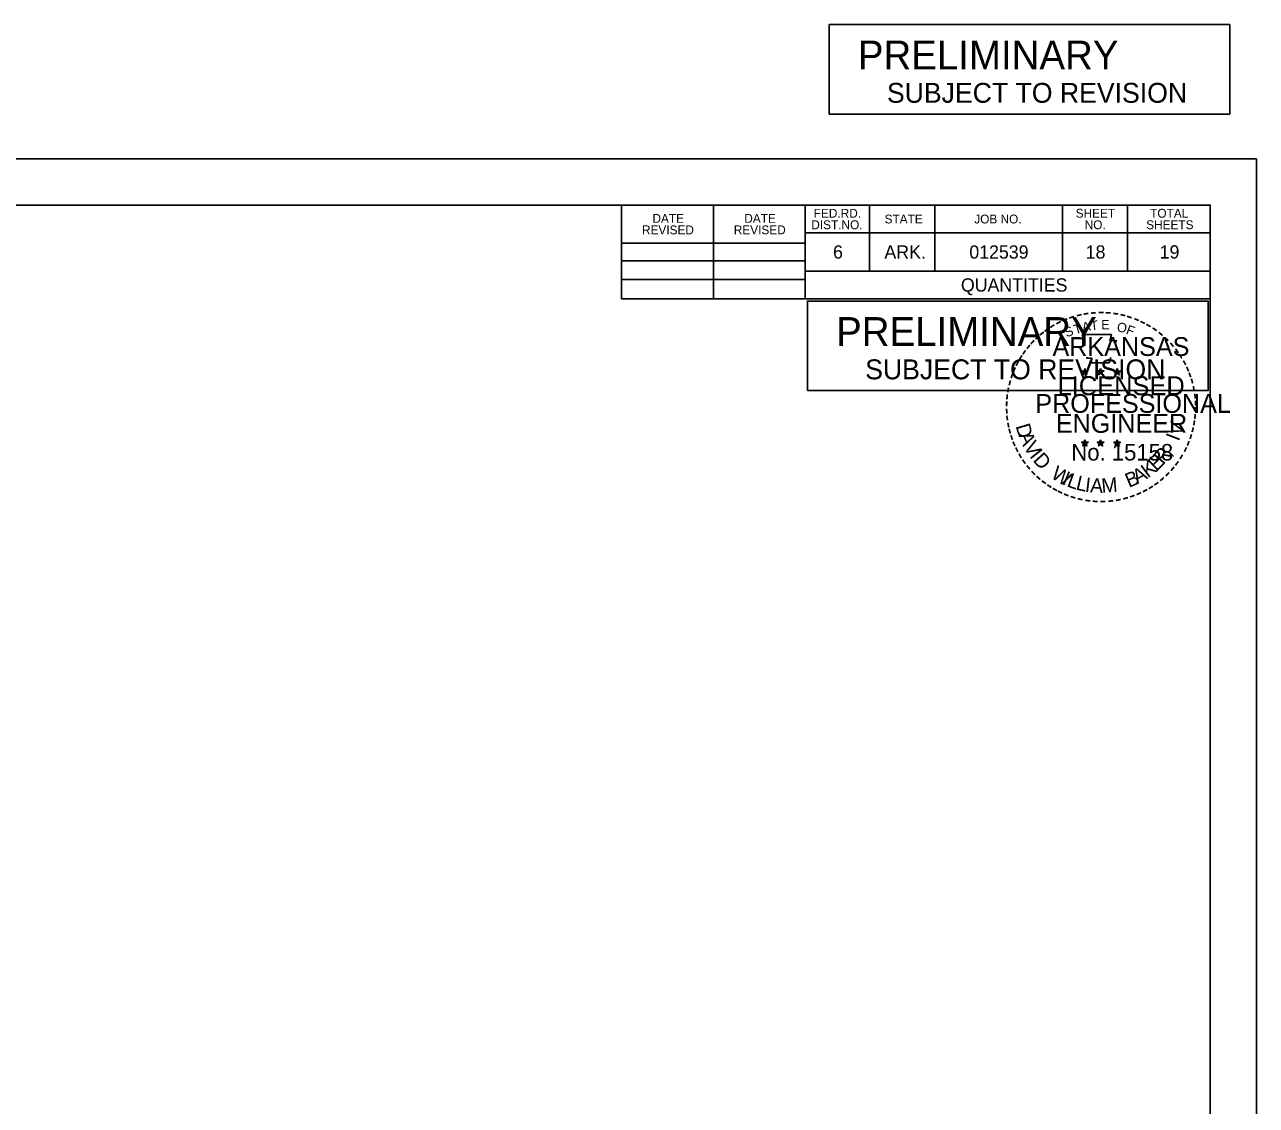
# Model space of a CAD drawing. Extents: x 0 to 1.72, y 0 to 0.98.
# Drawn here: x 0.86 to 1.417, y 0.489 to 0.977 of the extents above; entities that cross this region are included whole.
import ezdxf

# ---------------------------------------------------------------- set-up
doc = ezdxf.new("R2010")
doc.units = 0
for name, color, linetype in [('Default', 7, 'Continuous'), ('R_Border PE', 7, 'Continuous'), ('SHET_Annotations', 7, 'Continuous'), ('SHET_Border-Lines', 7, 'Continuous'), ('SHET_Border-Text', 7, 'Continuous'), ('SHET_Stamp-Prelim', 7, 'Continuous'), ('SHET_Stamp-Seal', 7, 'Continuous')]:
    doc.layers.add(name, color=color, linetype=linetype)

msp = doc.modelspace()

# ---------------------------------------------------------------- linework, layer by layer
at = {"layer": 'Default'}
msp.add_lwpolyline([(1.22349, 0.93697), (1.40466, 0.93697), (1.40466, 0.97742), (1.22349, 0.97742)], close=True, dxfattribs=at)
at = {"layer": 'SHET_Border-Lines'}
for p, q in [((1.12962, 0.85338), (1.12962, 0.89583)), ((1.17114, 0.85338), (1.17114, 0.89583)), ((1.21266, 0.89583), (1.21266, 0.85338)), ((1.24173, 0.89583), (1.24173, 0.86601)), ((1.27123, 0.89583), (1.27123, 0.86601)), ((1.32894, 0.89583), (1.32894, 0.86601)), ((1.35843, 0.89583), (1.35843, 0.86601)), ((1.39583, 0.8832), (1.21266, 0.8832)), ((1.39583, 0.88329), (1.39583, 0.88329)), ((1.12962, 0.87856), (1.21266, 0.87856)), ((1.12962, 0.87057), (1.21266, 0.87057)), ((1.39583, 0.86601), (1.21266, 0.86601)), ((1.22524, 0.86601), (1.39583, 0.86601)), ((1.12962, 0.86223), (1.21266, 0.86223)), ((1.39583, 0.85338), (1.12962, 0.85338))]:
    msp.add_line(p, q, dxfattribs=at)
for points in [[(0, 0), (1.41667, 0), (1.41667, 0.91667), (0, 0.91667)], [(0.02083, 0.02083), (1.39583, 0.02083), (1.39583, 0.89583), (0.02083, 0.89583)], [(1.12962, 0.85338), (1.39583, 0.85338), (1.39583, 0.89583), (1.12962, 0.89583)]]:
    msp.add_lwpolyline(points, close=True, dxfattribs=at)
at = {"layer": 'SHET_Stamp-Prelim'}
msp.add_lwpolyline([(1.21366, 0.81193), (1.39483, 0.81193), (1.39483, 0.85238), (1.21366, 0.85238)], close=True, dxfattribs=at)
at = {"layer": 'SHET_Stamp-Seal'}
for p, q in [((1.33768, 0.82084), (1.33916, 0.82037)), ((1.33768, 0.82084), (1.33875, 0.82065)), ((1.33768, 0.82084), (1.33869, 0.82032)), ((1.33824, 0.81911), (1.33916, 0.82037)), ((1.33824, 0.81911), (1.33878, 0.82014)), ((1.33824, 0.81911), (1.33915, 0.82003)), ((1.33916, 0.82192), (1.33899, 0.82085)), ((1.34007, 0.81911), (1.33915, 0.82002)), ((1.33916, 0.82037), (1.33916, 0.82192)), ((1.33916, 0.82192), (1.33937, 0.82086)), ((1.34064, 0.82084), (1.33916, 0.82037)), ((1.34007, 0.81911), (1.33916, 0.82037)), ((1.34064, 0.82084), (1.33942, 0.82063)), ((1.34007, 0.81911), (1.33948, 0.82034)), ((1.34064, 0.82084), (1.33977, 0.82041)), ((1.34478, 0.82084), (1.34626, 0.82037)), ((1.34478, 0.82084), (1.34585, 0.82065)), ((1.34478, 0.82084), (1.34578, 0.82032)), ((1.34534, 0.81911), (1.34626, 0.82037)), ((1.34534, 0.81911), (1.34588, 0.82014)), ((1.34534, 0.81911), (1.34625, 0.82003)), ((1.34626, 0.82192), (1.34608, 0.82085)), ((1.34716, 0.81911), (1.34625, 0.82002)), ((1.34626, 0.82037), (1.34626, 0.82192)), ((1.34626, 0.82192), (1.34647, 0.82086)), ((1.34773, 0.82084), (1.34626, 0.82037)), ((1.34716, 0.81911), (1.34626, 0.82037)), ((1.34773, 0.82084), (1.34652, 0.82063)), ((1.34716, 0.81911), (1.34658, 0.82034)), ((1.34773, 0.82084), (1.34687, 0.82041)), ((1.35227, 0.82079), (1.35376, 0.82032)), ((1.35227, 0.82079), (1.35335, 0.8206)), ((1.35227, 0.82079), (1.35328, 0.82027)), ((1.35284, 0.81906), (1.35376, 0.82032)), ((1.35284, 0.81906), (1.35337, 0.82009)), ((1.35284, 0.81906), (1.35375, 0.81998)), ((1.35376, 0.82187), (1.35358, 0.8208)), ((1.35466, 0.81906), (1.35375, 0.81997)), ((1.35376, 0.82032), (1.35376, 0.82187)), ((1.35376, 0.82187), (1.35396, 0.82081)), ((1.35523, 0.82079), (1.35376, 0.82032)), ((1.35466, 0.81906), (1.35376, 0.82032)), ((1.35523, 0.82079), (1.35402, 0.82058)), ((1.35466, 0.81906), (1.35408, 0.82029)), ((1.35523, 0.82079), (1.35436, 0.82036)), ((1.33766, 0.78866), (1.33914, 0.78818)), ((1.33766, 0.78866), (1.33874, 0.78846)), ((1.33766, 0.78866), (1.33867, 0.78814)), ((1.33823, 0.78692), (1.33914, 0.78818)), ((1.33823, 0.78692), (1.33876, 0.78796)), ((1.33823, 0.78692), (1.33914, 0.78784)), ((1.33914, 0.78974), (1.33897, 0.78866)), ((1.33914, 0.78818), (1.33914, 0.78974)), ((1.33914, 0.78974), (1.33935, 0.78867)), ((1.34062, 0.78866), (1.33914, 0.78818)), ((1.34005, 0.78692), (1.33914, 0.78818)), ((1.34005, 0.78692), (1.33914, 0.78783)), ((1.34062, 0.78866), (1.3394, 0.78845)), ((1.34005, 0.78692), (1.33947, 0.78816)), ((1.34062, 0.78866), (1.33975, 0.78822)), ((1.34475, 0.78866), (1.34624, 0.78818)), ((1.34475, 0.78866), (1.34583, 0.78846)), ((1.34475, 0.78866), (1.34576, 0.78814)), ((1.34532, 0.78692), (1.34624, 0.78818)), ((1.34532, 0.78692), (1.34586, 0.78796)), ((1.34532, 0.78692), (1.34623, 0.78784)), ((1.34624, 0.78974), (1.34606, 0.78866)), ((1.34714, 0.78692), (1.34623, 0.78783)), ((1.34624, 0.78818), (1.34624, 0.78974)), ((1.34624, 0.78974), (1.34645, 0.78867)), ((1.34771, 0.78866), (1.34624, 0.78818)), ((1.34714, 0.78692), (1.34624, 0.78818)), ((1.34771, 0.78866), (1.3465, 0.78845)), ((1.34714, 0.78692), (1.34656, 0.78816)), ((1.34771, 0.78866), (1.34685, 0.78822)), ((1.35226, 0.78861), (1.35375, 0.78814)), ((1.35226, 0.78861), (1.35334, 0.78842)), ((1.35226, 0.78861), (1.35327, 0.78809)), ((1.35283, 0.78688), (1.35375, 0.78814)), ((1.35283, 0.78688), (1.35336, 0.78792)), ((1.35283, 0.78688), (1.35374, 0.7878)), ((1.35375, 0.78969), (1.35357, 0.78862)), ((1.35465, 0.78688), (1.35374, 0.78779)), ((1.35375, 0.78814), (1.35375, 0.78969)), ((1.35375, 0.78969), (1.35396, 0.78863)), ((1.35522, 0.78861), (1.35375, 0.78814)), ((1.35465, 0.78688), (1.35375, 0.78814)), ((1.35522, 0.78861), (1.35401, 0.78841)), ((1.35465, 0.78688), (1.35407, 0.78812)), ((1.35522, 0.78861), (1.35436, 0.78818))]:
    msp.add_line(p, q, dxfattribs=at)
for points in [[(1.33785, 0.83732), (1.339, 0.83381)], [(1.35277, 0.8334), (1.35338, 0.83461), (1.35047, 0.83451), (1.3511, 0.83732), (1.33785, 0.83732)], [(1.33994, 0.82702), (1.33994, 0.82665), (1.34234, 0.82657), (1.34211, 0.82456), (1.35005, 0.82456), (1.35091, 0.82684)], [(1.34626, 0.82192), (1.34716, 0.81911), (1.34478, 0.82084), (1.34773, 0.82084), (1.34534, 0.81911), (1.34626, 0.82192)], [(1.35376, 0.82187), (1.35466, 0.81906), (1.35227, 0.82079), (1.35523, 0.82079), (1.35284, 0.81906), (1.35376, 0.82187)], [(1.33914, 0.78974), (1.34005, 0.78692), (1.33766, 0.78866), (1.34062, 0.78866), (1.33823, 0.78692), (1.33914, 0.78974)], [(1.34624, 0.78974), (1.34714, 0.78692), (1.34475, 0.78866), (1.34771, 0.78866), (1.34532, 0.78692), (1.34624, 0.78974)], [(1.35375, 0.78969), (1.35465, 0.78688), (1.35226, 0.78861), (1.35522, 0.78861), (1.35283, 0.78688), (1.35375, 0.78969)]]:
    msp.add_lwpolyline(points, dxfattribs=at)
for centre, radius in [((1.33916, 0.82037), 0.000732), ((1.33916, 0.82037), 0.000614), ((1.33916, 0.82037), 0.000492), ((1.33916, 0.82037), 0.000421), ((1.33916, 0.82037), 0.000318), ((1.33916, 0.82037), 0.000211), ((1.33916, 0.82037), 0.000126), ((1.34625, 0.82037), 0.000732), ((1.34625, 0.82037), 0.000614), ((1.34625, 0.82037), 0.000492), ((1.34625, 0.82037), 0.000421), ((1.34625, 0.82037), 0.000318), ((1.34625, 0.82037), 0.000211), ((1.34625, 0.82037), 0.000126), ((1.35375, 0.82031), 0.000732), ((1.35375, 0.82031), 0.000614), ((1.35375, 0.82031), 0.000492), ((1.35375, 0.82031), 0.000421), ((1.35375, 0.82031), 0.000318), ((1.35375, 0.82031), 0.000211), ((1.35375, 0.82031), 0.000126), ((1.33914, 0.78818), 0.000732), ((1.33914, 0.78818), 0.000614), ((1.33914, 0.78818), 0.000492), ((1.33914, 0.78818), 0.000421), ((1.33914, 0.78818), 0.000318), ((1.33914, 0.78818), 0.000211), ((1.33914, 0.78818), 0.000126), ((1.34623, 0.78818), 0.000732), ((1.34623, 0.78818), 0.000614), ((1.34623, 0.78818), 0.000492), ((1.34623, 0.78818), 0.000421), ((1.34623, 0.78818), 0.000318), ((1.34623, 0.78818), 0.000211), ((1.34623, 0.78818), 0.000126), ((1.35374, 0.78814), 0.000732), ((1.35374, 0.78814), 0.000614), ((1.35374, 0.78814), 0.000492), ((1.35374, 0.78814), 0.000421), ((1.35374, 0.78814), 0.000318), ((1.35374, 0.78814), 0.000211), ((1.35374, 0.78814), 0.000126)]:
    msp.add_circle(centre, radius, dxfattribs=at)

# ---------------------------------------------------------------- texts
at = {"layer": 'Default'}
for s, height, p in [('PRELIMINARY', 0.013, (1.23646, 0.9572)), ('SUBJECT TO REVISION', 0.009, (1.2496, 0.94208))]:
    msp.add_text(s, height=height, dxfattribs=at).set_placement(p)
at = {"layer": 'R_Border PE'}
msp.add_text('LICENSED', height=0.008594, dxfattribs=at).set_placement((1.3268, 0.80985))
at = {"layer": 'SHET_Annotations'}
for s, p in [('6', (1.22524, 0.87161)), ('ARK.', (1.24847, 0.87161)), ('012539', (1.28687, 0.87161)), ('18', (1.33949, 0.87161)), ('19', (1.37295, 0.87165)), ('QUANTITIES', (1.28307, 0.8567))]:
    msp.add_text(s, height=0.006, dxfattribs=at).set_placement(p)
at = {"layer": 'SHET_Border-Text'}
for s, p in [('DATE', (1.14358, 0.8878)), ('DATE', (1.1851, 0.8878)), ('FED.RD.', (1.21651, 0.89012)), ('STATE', (1.24854, 0.88752)), ('JOB NO.', (1.2891, 0.88752)), ('SHEET', (1.33496, 0.89012)), ('TOTAL', (1.36864, 0.89012)), ('REVISED', (1.13885, 0.8826)), ('REVISED', (1.18037, 0.8826)), ('DIST.NO.', (1.21541, 0.88492)), ('NO.', (1.33903, 0.88492)), ('SHEETS', (1.36685, 0.88492))]:
    msp.add_text(s, height=0.004, dxfattribs=at).set_placement(p)
at = {"layer": 'SHET_Stamp-Prelim'}
for s, height, p in [('PRELIMINARY', 0.013, (1.22663, 0.83215)), ('SUBJECT TO REVISION', 0.009, (1.23978, 0.81704))]:
    msp.add_text(s, height=height, dxfattribs=at).set_placement(p)
at = {"layer": 'SHET_Stamp-Seal'}
for s, height, rotation, p in [('-', 0.0068, 13.6302, (1.33572, 0.84314)), ('-', 0.0068, 10.2193, (1.3386, 0.84382)), ('-', 0.0068, 5.8968, (1.3417, 0.84429)), ('-', 0.0068, 0.1862, (1.34498, 0.8446)), ('-', 0.0068, 357.743, (1.34805, 0.84454)), ('-', 0.0068, 352.1617, (1.35121, 0.8443)), ('-', 0.0068, 347.2049, (1.35427, 0.84382)), ('-', 0.0068, 34.0636, (1.32461, 0.83805)), ('-', 0.0068, 28.7918, (1.32715, 0.83962)), ('-', 0.0068, 24.3072, (1.32984, 0.84097)), ('-', 0.0068, 19.1761, (1.33253, 0.84211)), ('T', 0.00425, 16.4036, (1.33475, 0.83736)), ('A', 0.00425, 11.2132, (1.33826, 0.83843)), ('T', 0.00425, 6.0228, (1.34186, 0.83913)), ('E', 0.00425, 0.8323, (1.34656, 0.8396)), ('O', 0.00425, 350.4515, (1.35338, 0.83871)), ('F', 0.00425, 340.0707, (1.35743, 0.83774)), ('-', 0.0068, 342.3362, (1.35697, 0.84316)), ('-', 0.0068, 337.8551, (1.36009, 0.84221)), ('-', 0.0068, 334.1211, (1.36277, 0.84106)), ('-', 0.0068, 329.6409, (1.36523, 0.83986)), ('-', 0.0068, 42.9622, (1.31829, 0.83299)), ('-', 0.0068, 38.9507, (1.32013, 0.83476)), ('-', 0.0068, 36.2317, (1.32215, 0.83637)), ('S', 0.00425, 21.594, (1.33086, 0.83595)), ('-', 0.0068, 325.8627, (1.36797, 0.83832)), ('-', 0.0068, 320.5297, (1.37056, 0.83651)), ('-', 0.0068, 315.5786, (1.3731, 0.83444)), ('-', 0.0068, 54.2325, (1.31292, 0.82648)), ('-', 0.0068, 50.6142, (1.31467, 0.82889)), ('-', 0.0068, 48.4231, (1.31639, 0.83096)), ('-', 0.0068, 309.8797, (1.37552, 0.8321)), ('-', 0.0068, 306.6522, (1.37775, 0.82954)), ('-', 0.0068, 62.8713, (1.31021, 0.82164)), ('-', 0.0068, 58.0706, (1.31154, 0.82424)), ('-', 0.00595, 303.6753, (1.37982, 0.82713)), ('-', 0.0068, 299.6684, (1.38118, 0.82455)), ('-', 0.0068, 72.3945, (1.30817, 0.81636)), ('-', 0.0068, 67.7743, (1.30911, 0.81904)), ('-', 0.0068, 294.6628, (1.38255, 0.82195)), ('-', 0.0068, 290.5728, (1.38364, 0.8195)), ('-', 0.0068, 81.2013, (1.30678, 0.8103)), ('-', 0.0068, 75.461, (1.30734, 0.81333)), ('-', 0.0068, 285.1233, (1.38464, 0.81703)), ('-', 0.0068, 280.5493, (1.38549, 0.81388)), ('-', 0.0068, 85.1863, (1.30645, 0.80736)), ('-', 0.0068, 276.5962, (1.38618, 0.81062)), ('-', 0.0068, 94.1959, (1.3065, 0.8013)), ('-', 0.0068, 89.0622, (1.30635, 0.80438)), ('-', 0.0068, 274.3301, (1.38643, 0.80755)), ('-', 0.0068, 269.9407, (1.38658, 0.80486)), ('-', 0.0068, 98.9479, (1.3068, 0.79846)), ('-', 0.0068, 101.7149, (1.30738, 0.79535)), ('D', 0.00654, 286.2848, (1.30775, 0.79594)), ('V', 0.00654, 72.6573, (1.38252, 0.791)), ('-', 0.0068, 260.9953, (1.38619, 0.79925)), ('-', 0.0068, 263.5172, (1.3865, 0.80203)), ('-', 0.0068, 105.4578, (1.30806, 0.79282)), ('-', 0.0068, 109.0874, (1.30898, 0.79014)), ('A', 0.00654, 292.7835, (1.309, 0.79168)), ('I', 0.00654, 69.0301, (1.38157, 0.78871)), ('-', 0.0068, 252.8681, (1.38496, 0.79331)), ('-', 0.0068, 255.7626, (1.38573, 0.79637)), ('-', 0.0068, 114.0643, (1.31006, 0.78761)), ('-', 0.0068, 115.7289, (1.31135, 0.78498)), ('V', 0.00654, 300.7936, (1.31118, 0.78667)), ('I', 0.00654, 308.3502, (1.31386, 0.78226)), ('R', 0.00654, 50.3651, (1.37456, 0.77814)), ('-', 0.0068, 244.6197, (1.3829, 0.78778)), ('-', 0.0068, 247.8887, (1.38401, 0.79045)), ('-', 0.0068, 120.4471, (1.31287, 0.78249)), ('-', 0.0068, 125.8934, (1.31458, 0.78011)), ('D', 0.00654, 311.9774, (1.31535, 0.78028)), ('K', 0.00654, 36.9143, (1.36758, 0.77219)), ('E', 0.00654, 44.0175, (1.37144, 0.77513)), (',', 0.00654, 57.4684, (1.37763, 0.78189)), ('-', 0.0068, 233.8452, (1.37951, 0.78181)), ('-', 0.0068, 239.0712, (1.38122, 0.78458)), ('-', 0.0068, 130.7181, (1.31655, 0.77776)), ('-', 0.0068, 134.2238, (1.31874, 0.77544)), ('W', 0.00654, 328.0731, (1.32334, 0.77278)), ('I', 0.00654, 336.6877, (1.32838, 0.76976)), ('L', 0.00654, 340.3149, (1.33063, 0.76872)), ('B', 0.00654, 22.8589, (1.35902, 0.7679)), ('A', 0.00654, 28.9042, (1.36283, 0.76949)), ('-', 0.0068, 225.7653, (1.37565, 0.777)), ('-', 0.0068, 231.2538, (1.37769, 0.7794)), ('-', 0.0068, 138.9338, (1.32098, 0.77347)), ('-', 0.0068, 144.6463, (1.32334, 0.77175)), ('-', 0.0068, 148.0898, (1.32572, 0.77017)), ('L', 0.00654, 346.6625, (1.33471, 0.76726)), ('I', 0.00654, 353.0101, (1.33893, 0.76625)), ('A', 0.00654, 356.6373, (1.34138, 0.76589)), ('M', 0.00654, 4.6473, (1.34684, 0.76564)), ('-', 0.0068, 212.2491, (1.36883, 0.77119)), ('-', 0.0068, 215.7363, (1.3711, 0.77283)), ('-', 0.0068, 221.0851, (1.37343, 0.77484)), ('-', 0.0068, 151.5704, (1.32818, 0.76879)), ('-', 0.0068, 154.6002, (1.3304, 0.76774)), ('-', 0.0068, 158.5612, (1.33305, 0.76666)), ('-', 0.0068, 162.7983, (1.33597, 0.76575)), ('-', 0.0068, 167.5555, (1.33901, 0.76506)), ('-', 0.0068, 195.4743, (1.3583, 0.76617)), ('-', 0.0068, 199.4643, (1.36112, 0.76718)), ('-', 0.0068, 204.2516, (1.36381, 0.76836)), ('-', 0.0068, 207.3568, (1.36646, 0.76972)), ('-', 0.0068, 173.1155, (1.34229, 0.76459)), ('-', 0.0068, 176.5183, (1.34547, 0.76436)), ('-', 0.0068, 181.5918, (1.34863, 0.76444)), ('-', 0.0068, 185.8167, (1.35207, 0.76477)), ('-', 0.0068, 191.2858, (1.3552, 0.76533))]:
    msp.add_text(s, height=height, rotation=rotation, dxfattribs=at).set_placement(p)
for s, height, p in [('ARKANSAS', 0.0085, (1.32448, 0.8276)), ('PROFESSIONAL', 0.0084998, (1.31672, 0.80187)), ('ENGINEER', 0.0085, (1.32601, 0.79284)), ('No. 15158', 0.007467, (1.33299, 0.7803)), ('AAMU', 0.000000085, (1.34596, 0.76562))]:
    msp.add_text(s, height=height, dxfattribs=at).set_placement(p)

doc.saveas('drawing.dxf')
